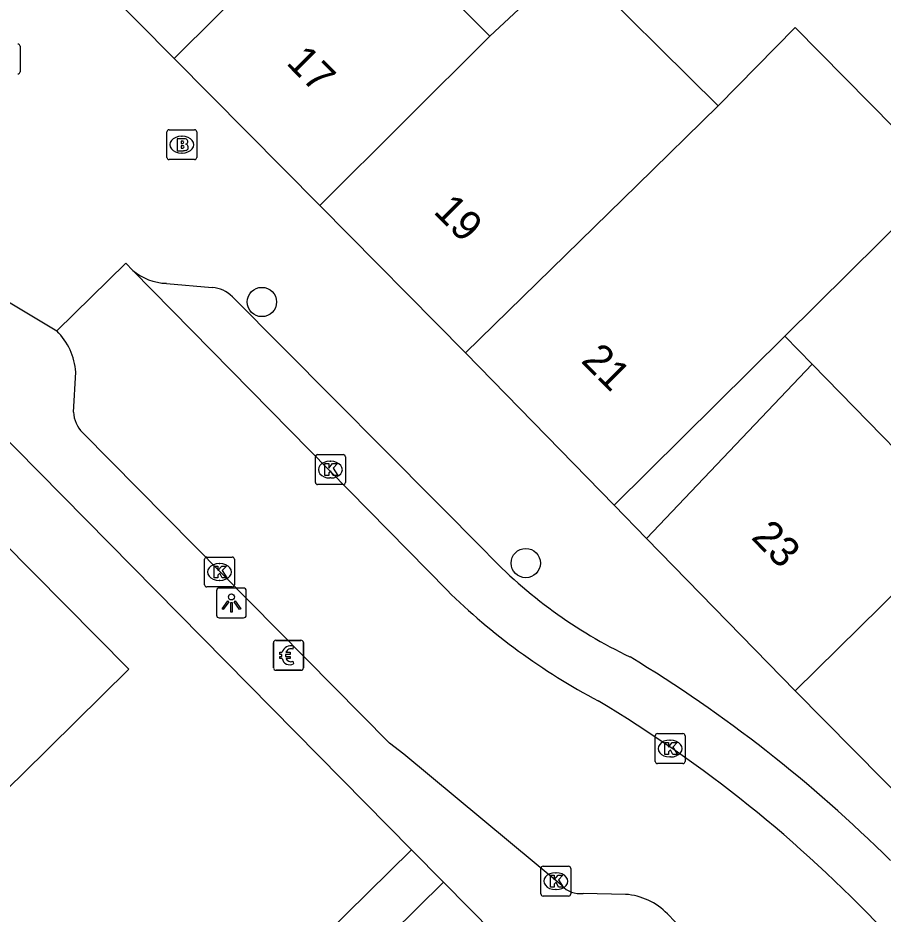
# Model space of a CAD drawing. Extents: x 160107 to 160928, y 382056 to 382918.
# Drawn here: x 160648.6 to 160677.52, y 382634.56 to 382664.5 of the extents above; entities that cross this region are included whole.
import ezdxf

# ---------------------------------------------------------------- set-up
doc = ezdxf.new("R2010")
doc.units = 0
for name, color, linetype in [('IMGEO_Betaalautomaat', 7, 'Continuous'), ('IMGEO_Boom', 7, 'Continuous'), ('IMGEO_Brandkraan', 7, 'Continuous'), ('IMGEO_Kolk', 7, 'Continuous'), ('IMGEO_Lichtpunt', 7, 'Continuous'), ('IMGEO_Pand', 7, 'Continuous'), ('IMGEO_Pand_nummerreeks', 7, 'Continuous'), ('IMGEO_Pand_overbouw', 7, 'Continuous'), ('IMGEO_Rijbaan_lokaal_open', 7, 'Continuous'), ('IMGEO_Rioolput', 7, 'Continuous'), ('IMGEO_Voetpad_open', 7, 'Continuous')]:
    doc.layers.add(name, color=color, linetype=linetype)

msp = doc.modelspace()

# ---------------------------------------------------------------- linework, layer by layer
at = {"layer": 'IMGEO_Betaalautomaat'}
for p, q in [((160657.145, 382642.781), (160657.145, 382643.622)), ((160657.145, 382643.622), (160657.145, 382642.781)), ((160657.22, 382643.705), (160658.061, 382643.705)), ((160658.061, 382643.705), (160657.22, 382643.705)), ((160657.807, 382643.51), (160657.79, 382643.41)), ((160658.144, 382643.631), (160658.144, 382642.79)), ((160658.144, 382642.79), (160658.144, 382643.631)), ((160657.428, 382643.169), (160657.428, 382643.237)), ((160657.549, 382643.237), (160657.549, 382643.169)), ((160657.794, 382643.004), (160657.816, 382642.917)), ((160658.07, 382642.706), (160657.229, 382642.706)), ((160657.229, 382642.706), (160658.07, 382642.706))]:
    msp.add_line(p, q, dxfattribs=at)
for points in [[(160657.428, 382643.237), (160657.359, 382643.237), (160657.359, 382643.306), (160657.438, 382643.306)], [(160657.56, 382643.306), (160657.707, 382643.306), (160657.707, 382643.237), (160657.549, 382643.237)], [(160657.433, 382643.1), (160657.359, 382643.1), (160657.359, 382643.169), (160657.428, 382643.169)], [(160657.549, 382643.169), (160657.707, 382643.169), (160657.707, 382643.1), (160657.563, 382643.1)]]:
    msp.add_lwpolyline(points, dxfattribs=at)
for centre, radius, start, end in [((160657.223, 382643.628), 0.0779, 92.4484, 184.2845), ((160657.223, 382643.628), 0.0779, 92.4484, 184.2845), ((160657.721, 382643.23), 0.293, 73.014, 165.0139), ((160658.067, 382643.628), 0.0779, 2.4484, 94.2845), ((160658.067, 382643.628), 0.0779, 2.4484, 94.2845), ((160657.727, 382643.243), 0.179, 69.3236, 159.5683), ((160657.694, 382643.155), 0.267, 191.8096, 297.0389), ((160657.727, 382643.17), 0.179, 202.7625, 291.8693), ((160657.223, 382642.784), 0.0779, 182.4484, 274.2845), ((160657.223, 382642.784), 0.0779, 182.4484, 274.2845), ((160658.067, 382642.784), 0.0779, 272.4484, 4.2845), ((160658.067, 382642.784), 0.0779, 272.4484, 4.2845)]:
    msp.add_arc(centre, radius, start, end, dxfattribs=at)
at = {"layer": 'IMGEO_Boom'}
for centre in [(160656.758, 382655.009), (160665.578, 382646.287)]:
    msp.add_circle(centre, 0.489, dxfattribs=at)
at = {"layer": 'IMGEO_Brandkraan'}
for p, q in [((160653.58, 382659.839), (160653.58, 382660.691)), ((160653.655, 382660.765), (160654.507, 382660.765)), ((160654.581, 382660.691), (160654.581, 382659.839)), ((160654.068, 382660.545), (160654.093, 382660.545)), ((160654.091, 382659.985), (160654.066, 382659.985)), ((160654.507, 382659.765), (160653.655, 382659.765))]:
    msp.add_line(p, q, dxfattribs=at)
for points in [[(160653.58, 382659.839), (160653.58, 382660.691)], [(160653.655, 382660.765), (160654.507, 382660.765)], [(160654.581, 382660.691), (160654.581, 382659.839)], [(160653.928, 382660.465), (160653.928, 382660.065), (160654.141, 382660.065)], [(160654.159, 382660.465), (160653.928, 382660.465)], [(160654.107, 382660.384), (160654.053, 382660.384), (160654.053, 382660.308)], [(160654.053, 382660.308), (160654.106, 382660.308)], [(160654.115, 382660.232), (160654.053, 382660.232), (160654.053, 382660.151)], [(160654.053, 382660.151), (160654.115, 382660.151)], [(160654.507, 382659.765), (160653.655, 382659.765)]]:
    msp.add_lwpolyline(points, dxfattribs=at)
for centre, radius, start, end in [((160653.657, 382660.689), 0.0765, 91.552, 178.448), ((160653.657, 382660.689), 0.0765, 91.552, 178.448), ((160654.505, 382660.689), 0.0765, 1.552, 88.448), ((160654.505, 382660.689), 0.0765, 1.552, 88.448), ((160654.108, 382660.346), 0.0379, 267.8285, 90.9355), ((160654.163, 382660.32), 0.145, 59.4692, 91.5367), ((160654.188, 382660.367), 0.0922, 285.5137, 58.1501), ((160654.193, 382660.175), 0.105, 301.3115, 78.989), ((160654.116, 382660.191), 0.0404, 269.8759, 90.5077), ((160654.147, 382660.316), 0.251, 268.6676, 293.5347), ((160653.657, 382659.841), 0.0765, 181.552, 268.448), ((160653.657, 382659.841), 0.0765, 181.552, 268.448), ((160654.505, 382659.841), 0.0765, 271.552, 358.448), ((160654.505, 382659.841), 0.0765, 271.552, 358.448)]:
    msp.add_arc(centre, radius, start, end, dxfattribs=at)
for centre, major_axis, ratio, start_param, end_param in [((160654.067, 382660.265), (-0.387, 0.002), 0.722429, 4.712389, 7.853982), ((160654.092, 382660.265), (-0.39, 0.002), 0.717154, 1.570796, 4.712389)]:
    msp.add_ellipse(centre, major_axis=major_axis, ratio=ratio, start_param=start_param, end_param=end_param, dxfattribs=at)
at = {"layer": 'IMGEO_Kolk'}
for p, q in [((160658.545, 382648.983), (160658.545, 382649.835)), ((160658.62, 382649.909), (160659.472, 382649.909)), ((160659.546, 382649.835), (160659.546, 382648.983)), ((160659.033, 382649.689), (160659.058, 382649.689)), ((160659.472, 382648.909), (160658.62, 382648.909)), ((160659.056, 382649.129), (160659.031, 382649.129)), ((160654.914, 382646.488), (160655.766, 382646.488)), ((160654.839, 382645.562), (160654.839, 382646.414)), ((160655.327, 382646.268), (160655.352, 382646.268)), ((160655.84, 382646.414), (160655.84, 382645.562)), ((160655.35, 382645.708), (160655.325, 382645.708)), ((160655.766, 382645.488), (160654.914, 382645.488)), ((160669.903, 382639.662), (160669.903, 382640.514)), ((160669.978, 382640.588), (160670.83, 382640.588)), ((160670.904, 382640.514), (160670.904, 382639.662)), ((160670.391, 382640.368), (160670.416, 382640.368)), ((160670.414, 382639.808), (160670.389, 382639.808)), ((160670.83, 382639.588), (160669.978, 382639.588)), ((160666.083, 382635.234), (160666.083, 382636.086)), ((160666.158, 382636.16), (160667.01, 382636.16)), ((160667.084, 382636.086), (160667.084, 382635.234)), ((160666.571, 382635.94), (160666.596, 382635.94)), ((160667.01, 382635.16), (160666.158, 382635.16)), ((160666.594, 382635.38), (160666.569, 382635.38))]:
    msp.add_line(p, q, dxfattribs=at)
for points in [[(160658.545, 382648.983), (160658.545, 382649.835)], [(160658.62, 382649.909), (160659.472, 382649.909)], [(160659.546, 382649.835), (160659.546, 382648.983)], [(160658.866, 382649.609), (160658.989, 382649.609), (160658.989, 382649.458), (160659.119, 382649.609), (160659.283, 382649.609), (160659.137, 382649.458), (160659.29, 382649.209), (160659.138, 382649.209), (160659.053, 382649.373), (160658.989, 382649.306), (160658.989, 382649.209), (160658.866, 382649.209), (160658.866, 382649.609)], [(160659.472, 382648.909), (160658.62, 382648.909)], [(160654.914, 382646.488), (160655.766, 382646.488)], [(160654.839, 382645.562), (160654.839, 382646.414)], [(160655.16, 382646.188), (160655.283, 382646.188), (160655.283, 382646.037), (160655.413, 382646.188), (160655.577, 382646.188), (160655.431, 382646.037), (160655.584, 382645.788), (160655.432, 382645.788), (160655.347, 382645.952), (160655.283, 382645.885), (160655.283, 382645.788), (160655.16, 382645.788), (160655.16, 382646.188)], [(160655.84, 382646.414), (160655.84, 382645.562)], [(160655.766, 382645.488), (160654.914, 382645.488)], [(160669.903, 382639.662), (160669.903, 382640.514)], [(160669.978, 382640.588), (160670.83, 382640.588)], [(160670.904, 382640.514), (160670.904, 382639.662)], [(160670.224, 382640.288), (160670.347, 382640.288), (160670.347, 382640.137), (160670.477, 382640.288), (160670.641, 382640.288), (160670.495, 382640.137), (160670.648, 382639.888), (160670.496, 382639.888), (160670.411, 382640.052), (160670.347, 382639.985), (160670.347, 382639.888), (160670.224, 382639.888), (160670.224, 382640.288)], [(160670.83, 382639.588), (160669.978, 382639.588)], [(160666.083, 382635.234), (160666.083, 382636.086)], [(160666.158, 382636.16), (160667.01, 382636.16)], [(160667.084, 382636.086), (160667.084, 382635.234)], [(160666.404, 382635.86), (160666.527, 382635.86), (160666.527, 382635.709), (160666.657, 382635.86), (160666.821, 382635.86), (160666.675, 382635.709), (160666.828, 382635.46), (160666.676, 382635.46), (160666.591, 382635.624), (160666.527, 382635.557), (160666.527, 382635.46), (160666.404, 382635.46), (160666.404, 382635.86)], [(160667.01, 382635.16), (160666.158, 382635.16)]]:
    msp.add_lwpolyline(points, dxfattribs=at)
for centre, start, end in [((160658.622, 382649.833), 91.552, 178.448), ((160658.622, 382649.833), 91.552, 178.448), ((160659.47, 382649.833), 1.552, 88.448), ((160659.47, 382649.833), 1.552, 88.448), ((160658.622, 382648.985), 181.552, 268.448), ((160658.622, 382648.985), 181.552, 268.448), ((160659.47, 382648.985), 271.552, 358.448), ((160659.47, 382648.985), 271.552, 358.448), ((160654.916, 382646.412), 91.552, 178.448), ((160654.916, 382646.412), 91.552, 178.448), ((160655.764, 382646.412), 1.552, 88.448), ((160655.764, 382646.412), 1.552, 88.448), ((160654.916, 382645.564), 181.552, 268.448), ((160654.916, 382645.564), 181.552, 268.448), ((160655.764, 382645.564), 271.552, 358.448), ((160655.764, 382645.564), 271.552, 358.448), ((160669.98, 382640.512), 91.552, 178.448), ((160669.98, 382640.512), 91.552, 178.448), ((160670.828, 382640.512), 1.552, 88.448), ((160670.828, 382640.512), 1.552, 88.448), ((160669.98, 382639.664), 181.552, 268.448), ((160669.98, 382639.664), 181.552, 268.448), ((160670.828, 382639.664), 271.552, 358.448), ((160670.828, 382639.664), 271.552, 358.448), ((160666.16, 382636.084), 91.552, 178.448), ((160666.16, 382636.084), 91.552, 178.448), ((160667.008, 382636.084), 1.552, 88.448), ((160667.008, 382636.084), 1.552, 88.448), ((160666.16, 382635.236), 181.552, 268.448), ((160666.16, 382635.236), 181.552, 268.448), ((160667.008, 382635.236), 271.552, 358.448), ((160667.008, 382635.236), 271.552, 358.448)]:
    msp.add_arc(centre, 0.0765, start, end, dxfattribs=at)
for centre, major_axis, ratio, start_param, end_param in [((160659.032, 382649.409), (-0.387, 0.002), 0.722429, 4.712389, 7.853982), ((160659.057, 382649.409), (-0.39, 0.002), 0.717154, 1.570796, 4.712389), ((160655.326, 382645.988), (-0.387, 0.002), 0.722429, 4.712389, 7.853982), ((160655.351, 382645.988), (-0.39, 0.002), 0.717154, 1.570796, 4.712389), ((160670.39, 382640.088), (-0.387, 0.002), 0.722429, 4.712389, 7.853982), ((160670.415, 382640.088), (-0.39, 0.002), 0.717154, 1.570796, 4.712389), ((160666.57, 382635.66), (-0.387, 0.002), 0.722429, 4.712389, 7.853982), ((160666.595, 382635.66), (-0.39, 0.002), 0.717154, 1.570796, 4.712389)]:
    msp.add_ellipse(centre, major_axis=major_axis, ratio=ratio, start_param=start_param, end_param=end_param, dxfattribs=at)
at = {"layer": 'IMGEO_Lichtpunt'}
for p, q in [((160655.239, 382645.357), (160655.239, 382644.55)), ((160655.239, 382645.357), (160655.239, 382644.55)), ((160656.141, 382645.452), (160655.333, 382645.452)), ((160656.141, 382645.452), (160655.333, 382645.452)), ((160656.235, 382644.55), (160656.235, 382645.357)), ((160656.235, 382644.55), (160656.235, 382645.357)), ((160655.333, 382644.456), (160656.141, 382644.456)), ((160655.333, 382644.456), (160656.141, 382644.456))]:
    msp.add_line(p, q, dxfattribs=at)
for points in [[(160655.613, 382645.021), (160655.652, 382644.993), (160655.464, 382644.731), (160655.426, 382644.758), (160655.613, 382645.021)], [(160655.825, 382644.993), (160655.863, 382645.02), (160656.05, 382644.758), (160656.011, 382644.73), (160655.825, 382644.993)], [(160655.715, 382644.973), (160655.762, 382644.973), (160655.762, 382644.651), (160655.715, 382644.651), (160655.715, 382644.973)]]:
    msp.add_lwpolyline(points, dxfattribs=at)
msp.add_circle((160655.738, 382645.155), 0.0994, dxfattribs=at)
for centre, start, end in [((160655.333, 382645.357), 90, 180), ((160655.333, 382645.357), 90, 180), ((160656.141, 382645.357), 0, 90), ((160656.141, 382645.357), 0, 90), ((160655.333, 382644.55), 180, 270), ((160655.333, 382644.55), 180, 270), ((160656.141, 382644.55), 270, 0), ((160656.141, 382644.55), 270, 360)]:
    msp.add_arc(centre, 0.0946, start, end, dxfattribs=at)
at = {"layer": 'IMGEO_Pand'}
for points in [[(160653.827, 382663.146), (160659.514, 382668.799)], [(160653.827, 382663.146), (160648.883, 382668.139)], [(160661.615, 382666.677), (160664.371, 382663.893)], [(160664.371, 382663.893), (160667.096, 382666.434), (160672.007, 382661.561)], [(160672.007, 382661.561), (160674.579, 382664.179), (160679.567, 382659.14), (160674.237, 382653.864), (160668.534, 382648.218)], [(160664.371, 382663.893), (160658.688, 382658.236)], [(160658.688, 382658.236), (160653.827, 382663.146)], [(160672.007, 382661.561), (160669.299, 382658.916), (160663.563, 382653.311)], [(160663.563, 382653.311), (160658.688, 382658.236)], [(160668.534, 382648.218), (160663.563, 382653.311)], [(160669.618, 382647.108), (160675.152, 382652.928), (160680.312, 382647.65)], [(160648.326, 382638.824), (160648.748, 382639.239), (160652.312, 382642.745), (160645.935, 382649.166), (160641.954, 382645.241)], [(160674.589, 382642.015), (160680.312, 382647.65)], [(160674.589, 382642.015), (160669.618, 382647.108)], [(160679.49, 382637.064), (160674.589, 382642.015)]]:
    msp.add_lwpolyline(points, dxfattribs=at)
at = {"layer": 'IMGEO_Pand_overbouw'}
msp.add_lwpolyline([(160675.152, 382652.928), (160674.237, 382653.864), (160668.534, 382648.218), (160669.618, 382647.108)], close=True, dxfattribs=at)
at = {"layer": 'IMGEO_Rijbaan_lokaal_open'}
for points in [[(160649.899, 382654.041), (160652.209, 382656.301), (160652.444, 382656.062)], [(160652.444, 382656.062), (160662.945, 382645.377)], [(160650.455, 382651.333), (160650.531, 382652.663)], [(160666.785, 382635.514), (160661.496, 382639.903), (160661.023, 382640.273), (160650.759, 382650.645)], [(160668.917, 382635.219), (160667.492, 382635.249)], [(160671.343, 382633.499), (160670.313, 382634.568)]]:
    msp.add_lwpolyline(points, dxfattribs=at)
for centre, radius, start, end in [((160648.439, 382652.537), 2.096, 3.4387, 45.8371), ((160651.514, 382651.39), 1.06, 183.0631, 224.6144), ((160678.099, 382660.798), 21.62, 225.5005, 242.1541), ((160645.108, 382603.375), 44.625, 43.4149, 59.1365), ((160667.383, 382636.035), 0.793, 221.042, 277.8636), ((160668.761, 382633.062), 2.162, 44.1318, 85.8659)]:
    msp.add_arc(centre, radius, start, end, dxfattribs=at)
at = {"layer": 'IMGEO_Rioolput'}
msp.add_line((160648.674, 382663.553), (160648.674, 382662.701), dxfattribs=at)
msp.add_lwpolyline([(160648.674, 382663.553), (160648.674, 382662.701)], dxfattribs=at)
for centre, start, end in [((160648.598, 382663.551), 1.552, 88.448), ((160648.598, 382663.551), 1.552, 88.448), ((160648.598, 382662.703), 271.552, 358.448), ((160648.598, 382662.703), 271.552, 358.448)]:
    msp.add_arc(centre, 0.0765, start, end, dxfattribs=at)
at = {"layer": 'IMGEO_Voetpad_open'}
for points in [[(160646.486, 382656.089), (160649.899, 382654.041)], [(160653.571, 382655.632), (160655.096, 382655.497)], [(160655.77, 382655.181), (160664.249, 382646.651)], [(160646.97, 382651.686), (160661.762, 382636.708)], [(160668.534, 382648.218), (160669.618, 382647.108)], [(160661.762, 382636.708), (160657.395, 382632.411)], [(160661.762, 382636.708), (160662.826, 382635.631)], [(160661.073, 382633.9), (160662.826, 382635.631)], [(160662.826, 382635.631), (160712.982, 382584.842)]]:
    msp.add_lwpolyline(points, dxfattribs=at)
for centre, radius, start, end in [((160653.62, 382657.454), 1.822, 229.7878, 268.4441), ((160655.003, 382654.422), 1.079, 44.7069, 85.0548), ((160676.044, 382657.828), 16.25, 223.4598, 244.5534), ((160644.698, 382603.008), 46.962, 45.2318, 58.7473)]:
    msp.add_arc(centre, radius, start, end, dxfattribs=at)

# ---------------------------------------------------------------- texts
at = {"layer": 'IMGEO_Pand_nummerreeks'}
for s, rotation, p in [('17', 314.7134, (160657.538, 382662.976)), ('19', 314.7133, (160662.461, 382658.006)), ('21', 314.7133, (160667.398, 382653.02)), ('23', 314.7138, (160673.083, 382647.118))]:
    msp.add_text(s, height=1, rotation=rotation, dxfattribs=at).set_placement(p)

doc.saveas('drawing.dxf')
